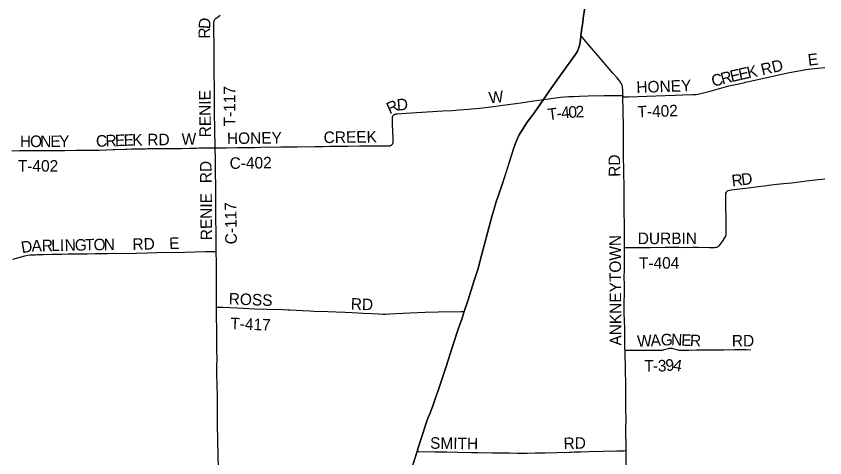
# Model space of a CAD drawing. Extents: x 40529 to 41139, y 15164 to 15584.
# Drawn here: x 40618.2 to 40737.7, y 15293.1 to 15358.4 of the extents above; entities that cross this region are included whole.
import ezdxf

# ---------------------------------------------------------------- set-up
doc = ezdxf.new("R2010")
doc.units = 0
for name, color, linetype in [('GM_X_County_Road', 7, 'Continuous'), ('GM_X_County_Road_Text', 7, 'Continuous'), ('GM_X_State_Route', 7, 'Continuous'), ('GM_X_Township_Road', 7, 'Continuous'), ('GM_X_Township_Road_Text', 7, 'Continuous'), ('SH_Data', 7, 'Continuous')]:
    doc.layers.add(name, color=color, linetype=linetype)

msp = doc.modelspace()

# ---------------------------------------------------------------- linework, layer by layer
at = {"layer": 'GM_X_County_Road'}
msp.add_line((40707.83, 15346.5), (40707.83, 15346.69), dxfattribs=at)
for points in [[(40707.83, 15346.69), (40707.83, 15346.91), (40707.81, 15347.56), (40707.79, 15347.85), (40707.76, 15348.03), (40707.71, 15348.22), (40707.68, 15348.3), (40707.6, 15348.48), (40707.5, 15348.64), (40707.39, 15348.79), (40706.98, 15349.3), (40706.37, 15350), (40704.11, 15352.61), (40703.2, 15353.67), (40702.59, 15354.37), (40701.8, 15355.29), (40701.69, 15355.43), (40701.63, 15355.51)], [(40647.63, 15338.98), (40647.76, 15338.97), (40649.24, 15338.97), (40650.91, 15338.99), (40652.03, 15339), (40653.42, 15339.02), (40654.44, 15339.04), (40657.32, 15339.1), (40658.25, 15339.11), (40659.75, 15339.12), (40662.35, 15339.15), (40663.56, 15339.17), (40664.59, 15339.19), (40665.7, 15339.19), (40667.19, 15339.21), (40668.96, 15339.23), (40671.01, 15339.25), (40673.16, 15339.24), (40673.34, 15339.25), (40673.43, 15339.27), (40673.52, 15339.29), (40673.6, 15339.33), (40673.68, 15339.37), (40673.74, 15339.43), (40673.79, 15339.5), (40673.84, 15339.58), (40673.87, 15339.66), (40673.89, 15339.75), (40673.9, 15339.84), (40673.91, 15340.03), (40673.9, 15340.4), (40673.82, 15342.45), (40673.8, 15343.19), (40673.8, 15343.38), (40673.81, 15343.48), (40673.83, 15343.57), (40673.87, 15343.66), (40673.92, 15343.74), (40673.99, 15343.81), (40674.07, 15343.87), (40674.15, 15343.92), (40674.24, 15343.95), (40674.34, 15343.97), (40674.53, 15343.99), (40675.83, 15344.07), (40681.23, 15344.41), (40682.63, 15344.5), (40683.65, 15344.56), (40685.04, 15344.67), (40685.5, 15344.71), (40686.15, 15344.78), (40687.13, 15344.89), (40688.7, 15345.09), (40690.09, 15345.24), (40692.03, 15345.49), (40692.77, 15345.6), (40693.69, 15345.76), (40694.33, 15345.86), (40694.68, 15345.9), (40695.41, 15346.02), (40695.78, 15346.07), (40696.11, 15346.12)], [(40708.08, 15324.23), (40708.08, 15324.78), (40708.09, 15325.01), (40708.09, 15326.32), (40708.08, 15326.69), (40708.06, 15327.71), (40708.04, 15329.39), (40708.02, 15332.09), (40708, 15333.4), (40707.96, 15335.17), (40707.93, 15338.24), (40707.9, 15342.16), (40707.85, 15344.39), (40707.83, 15346.5)], [(40647.78, 15323.65), (40647.78, 15324.04), (40647.77, 15324.79), (40647.75, 15326.18), (40647.74, 15328.78), (40647.72, 15329.9), (40647.7, 15332.78), (40647.67, 15335.85), (40647.65, 15337.24), (40647.63, 15338.98)], [(40617.73, 15322.51), (40618.27, 15322.64), (40619.53, 15323), (40619.98, 15323.1), (40620.25, 15323.16), (40620.72, 15323.16), (40621.05, 15323.17), (40621.32, 15323.18), (40621.55, 15323.2), (40621.73, 15323.2), (40621.93, 15323.21), (40622.21, 15323.21), (40623.51, 15323.24), (40625, 15323.26), (40625.93, 15323.27), (40627.51, 15323.3), (40627.88, 15323.31), (40628.71, 15323.31), (40629.92, 15323.34), (40631.47, 15323.35), (40631.7, 15323.35), (40632.74, 15323.37), (40632.99, 15323.36), (40635.96, 15323.41), (40637.64, 15323.43), (40639.03, 15323.47), (40643.13, 15323.56), (40646.2, 15323.62), (40647.23, 15323.63), (40647.6, 15323.64), (40647.78, 15323.65)], [(40708.15, 15309.08), (40708.14, 15309.15), (40708.12, 15310.83), (40708.1, 15312.13), (40708.05, 15313.61), (40708.02, 15314.44), (40708.02, 15315.26), (40708.03, 15315.91), (40708.05, 15317.57), (40708.05, 15318.69), (40708.04, 15319.9), (40708.06, 15320.88), (40708.08, 15321.52), (40708.08, 15322.36), (40708.09, 15323.1), (40708.08, 15323.66), (40708.08, 15324.23)], [(40708.32, 15294.22), (40708.31, 15295.05), (40708.29, 15296.81), (40708.29, 15297.37), (40708.3, 15298.86), (40708.28, 15300.25), (40708.27, 15300.9), (40708.27, 15301.16), (40708.27, 15302.73), (40708.25, 15304.22), (40708.22, 15305.89), (40708.15, 15309.08)], [(40708.47, 15279.32), (40708.45, 15279.8), (40708.45, 15280.02), (40708.44, 15280.23), (40708.44, 15280.51), (40708.42, 15283.4), (40708.42, 15283.96), (40708.42, 15284.62), (40708.41, 15286.02), (40708.38, 15287.08), (40708.34, 15289.41), (40708.34, 15289.95), (40708.34, 15290.3), (40708.33, 15290.78), (40708.31, 15291.87), (40708.32, 15292.45), (40708.33, 15294.12), (40708.32, 15294.22)]]:
    msp.add_lwpolyline(points, dxfattribs=at)
at = {"layer": 'GM_X_State_Route'}
for points in [[(40696.32, 15346.42), (40696.93, 15347.32), (40698.39, 15349.37), (40699.26, 15350.58), (40700.4, 15352.17), (40700.77, 15352.71), (40700.98, 15353.02), (40701.11, 15353.24), (40701.24, 15353.51), (40701.34, 15353.78), (40701.41, 15354.06), (40701.47, 15354.34), (40701.52, 15354.61), (40701.61, 15355.35), (40701.63, 15355.51), (40701.78, 15356.64), (40701.9, 15357.47), (40701.99, 15358.12), (40702.25, 15360)], [(40685.84, 15319.2), (40686.08, 15319.94), (40686.42, 15321), (40686.71, 15322.09), (40687.02, 15323.26), (40688.22, 15327.86), (40688.51, 15328.94), (40688.8, 15329.92), (40689.08, 15330.81), (40689.94, 15333.38), (40690.67, 15335.59), (40691.69, 15338.79), (40691.93, 15339.49), (40692.13, 15340.01), (40692.32, 15340.44), (40692.52, 15340.86), (40692.75, 15341.26), (40692.94, 15341.58), (40693.24, 15342.05), (40693.72, 15342.74), (40694.33, 15343.57), (40694.76, 15344.17), (40696.11, 15346.12), (40696.32, 15346.42)], [(40676.69, 15291.75), (40677.45, 15294.1), (40677.67, 15294.78), (40678.66, 15297.97), (40678.87, 15298.59), (40679.03, 15299.02), (40679.25, 15299.54), (40679.56, 15300.27), (40679.78, 15300.84), (40680.08, 15301.71), (40680.55, 15303.11), (40681.72, 15306.64), (40682.68, 15309.58), (40683.51, 15312.15), (40684.08, 15313.8), (40684.4, 15314.79), (40684.96, 15316.48), (40685.84, 15319.2)]]:
    msp.add_lwpolyline(points, dxfattribs=at)
at = {"layer": 'GM_X_Township_Road'}
msp.add_line((40707.83, 15346.69), (40707.83, 15346.5), dxfattribs=at)
for points in [[(40647.63, 15338.98), (40647.63, 15339.19), (40647.62, 15339.83), (40647.59, 15340.94), (40647.56, 15342.24), (40647.53, 15343.63), (40647.52, 15345.12), (40647.52, 15348.1), (40647.5, 15349.59), (40647.47, 15353.5), (40647.44, 15356.94), (40647.44, 15357.5), (40647.45, 15357.59), (40647.47, 15357.67), (40647.5, 15357.76), (40647.54, 15357.84), (40647.58, 15357.92), (40647.63, 15357.99), (40647.69, 15358.06), (40647.76, 15358.12), (40647.9, 15358.24), (40648.37, 15358.54)], [(40707.83, 15346.5), (40708.03, 15346.51), (40708.68, 15346.52), (40711.38, 15346.59), (40714.08, 15346.7), (40715.57, 15346.75), (40716.69, 15346.79), (40718.18, 15346.84), (40718.64, 15346.86), (40718.92, 15346.9), (40719.28, 15346.97), (40719.73, 15347.07), (40720.72, 15347.34), (40722.42, 15347.82), (40723.5, 15348.1), (40724.96, 15348.44), (40725.77, 15348.62), (40725.94, 15348.65), (40726.18, 15348.71), (40727.31, 15348.95), (40728.22, 15349.14), (40731.94, 15349.98), (40733.22, 15350.24), (40734.13, 15350.41), (40734.87, 15350.53), (40735.61, 15350.64), (40736.63, 15350.75), (40737.65, 15350.85)], [(40696.11, 15346.12), (40696.86, 15346.21), (40698.61, 15346.43), (40699.27, 15346.5), (40699.83, 15346.53), (40700.57, 15346.56), (40701.41, 15346.59), (40702.72, 15346.64), (40705.05, 15346.7), (40705.61, 15346.71), (40706.73, 15346.69), (40707.66, 15346.69), (40707.83, 15346.69)], [(40617.58, 15338.54), (40618.74, 15338.58), (40619.94, 15338.57), (40620.42, 15338.56), (40620.68, 15338.56), (40620.91, 15338.56), (40621.09, 15338.56), (40622, 15338.56), (40623.26, 15338.56), (40623.72, 15338.57), (40623.83, 15338.56), (40623.99, 15338.57), (40624.37, 15338.57), (40625.43, 15338.58), (40627.07, 15338.6), (40627.73, 15338.61), (40628.74, 15338.61), (40629.28, 15338.6), (40630.49, 15338.62), (40631.59, 15338.67), (40632.63, 15338.69), (40632.83, 15338.69), (40634.38, 15338.76), (40634.48, 15338.76), (40634.55, 15338.77), (40635.28, 15338.8), (40635.89, 15338.81), (40636.19, 15338.81), (40636.66, 15338.81), (40636.86, 15338.81), (40637.04, 15338.82), (40637.36, 15338.82), (40637.65, 15338.84), (40637.84, 15338.84), (40637.98, 15338.84), (40638.26, 15338.84), (40638.42, 15338.84), (40638.66, 15338.84), (40638.95, 15338.84), (40639.27, 15338.85), (40639.43, 15338.84), (40639.57, 15338.85), (40639.76, 15338.84), (40640.3, 15338.85), (40640.82, 15338.86), (40642.64, 15338.88), (40643.82, 15338.91), (40644.86, 15338.93), (40645.24, 15338.94), (40645.43, 15338.94), (40646.55, 15338.97), (40647.2, 15338.98), (40647.48, 15338.98), (40647.63, 15338.98)], [(40708.08, 15324.23), (40708.22, 15324.24), (40709.06, 15324.25), (40710.46, 15324.25), (40711.92, 15324.25), (40714.09, 15324.26), (40715.49, 15324.27), (40716.15, 15324.27), (40717.15, 15324.25), (40718.09, 15324.26), (40718.93, 15324.27), (40720.61, 15324.25), (40721.1, 15324.25), (40721.39, 15324.25), (40721.57, 15324.27), (40721.74, 15324.3), (40721.86, 15324.34), (40721.97, 15324.41), (40722.03, 15324.46), (40722.1, 15324.54), (40722.2, 15324.66), (40722.33, 15324.85), (40722.52, 15325.14), (40722.87, 15325.66), (40723.01, 15325.89), (40723.04, 15325.97), (40723.07, 15326.05), (40723.09, 15326.22), (40723.1, 15326.39), (40723.09, 15326.66), (40723.08, 15327.03), (40723.08, 15327.22), (40723.07, 15327.4), (40723.07, 15327.67), (40723.06, 15327.98), (40723.06, 15328.47), (40723.05, 15330.32), (40723.03, 15331.44), (40723.04, 15332.09), (40723.04, 15332.18), (40723.05, 15332.27), (40723.11, 15332.43), (40723.17, 15332.51), (40723.24, 15332.56), (40723.31, 15332.62), (40723.4, 15332.67), (40723.59, 15332.7), (40723.85, 15332.73), (40724.66, 15332.83), (40725.96, 15332.98), (40728.26, 15333.28), (40728.81, 15333.36), (40729.31, 15333.43), (40729.8, 15333.51), (40730.57, 15333.59), (40731.55, 15333.68), (40732.75, 15333.81), (40735.34, 15334.12), (40737.65, 15334.38)], [(40647.84, 15315.41), (40647.83, 15316.48), (40647.84, 15317.78), (40647.81, 15319.08), (40647.8, 15320.85), (40647.81, 15321.68), (40647.8, 15322.06), (40647.78, 15323.54), (40647.78, 15323.65)], [(40648.34, 15278.15), (40648.33, 15279.06), (40648.3, 15281.66), (40648.25, 15285.2), (40648.21, 15286.87), (40648.18, 15288.73), (40648.16, 15289.66), (40648.13, 15291.34), (40648.08, 15293.67), (40648.04, 15295.52), (40647.98, 15298.33), (40647.97, 15300.28), (40647.95, 15302.23), (40647.88, 15305.57), (40647.89, 15306.52), (40647.9, 15307.91), (40647.87, 15308.93), (40647.86, 15310.14), (40647.85, 15310.43), (40647.85, 15310.89), (40647.86, 15312.19), (40647.84, 15313.87), (40647.84, 15314.8), (40647.84, 15315.41)], [(40647.84, 15315.41), (40647.97, 15315.41), (40648.81, 15315.39), (40650.85, 15315.3), (40653.46, 15315.19), (40655.23, 15315.12), (40657.65, 15315.05), (40658.38, 15315.02), (40658.65, 15315), (40660.51, 15314.92), (40661.62, 15314.86), (40662.18, 15314.82), (40664.31, 15314.75), (40665.51, 15314.71), (40666.81, 15314.65), (40667.84, 15314.6), (40669.5, 15314.53), (40670.71, 15314.47), (40671.74, 15314.42), (40672.39, 15314.4), (40672.85, 15314.4), (40673.41, 15314.42), (40676.38, 15314.57), (40677.5, 15314.63), (40678.62, 15314.67), (40680.57, 15314.72), (40683.93, 15314.78), (40684.4, 15314.79)], [(40708.15, 15309.08), (40708.83, 15309.08), (40710.28, 15309.05), (40712.6, 15309.05), (40713.06, 15309.05), (40713.48, 15309.05), (40713.64, 15309.07), (40713.82, 15309.11), (40713.95, 15309.14), (40714.17, 15309.2), (40714.39, 15309.26), (40714.59, 15309.32), (40714.68, 15309.34), (40714.78, 15309.35), (40714.89, 15309.35), (40714.97, 15309.35), (40715.09, 15309.33), (40715.21, 15309.3), (40715.39, 15309.25), (40715.78, 15309.14), (40715.92, 15309.1), (40716.08, 15309.08), (40716.38, 15309.06), (40717.02, 15309.06), (40717.56, 15309.06), (40718.7, 15309.1), (40719.36, 15309.11), (40719.88, 15309.13), (40722.71, 15309.13), (40724.33, 15309.14), (40725.51, 15309.16), (40726.1, 15309.17), (40726.71, 15309.13)], [(40677.45, 15294.1), (40677.7, 15294.1), (40680.03, 15294.05), (40681.8, 15294.02), (40683.47, 15294), (40685.52, 15293.95), (40686.45, 15293.93), (40688.59, 15293.91), (40690.07, 15293.91), (40691.1, 15293.89), (40692.21, 15293.85), (40692.76, 15293.85), (40693.69, 15293.86), (40694.9, 15293.87), (40696.37, 15293.89), (40698.14, 15293.95), (40699.9, 15293.99), (40700.18, 15293.99), (40700.64, 15294.01), (40701.57, 15294.04), (40702.78, 15294.08), (40704.91, 15294.13), (40706.95, 15294.16), (40707.41, 15294.18), (40707.76, 15294.19), (40708.03, 15294.2), (40708.2, 15294.22), (40708.32, 15294.22)]]:
    msp.add_lwpolyline(points, dxfattribs=at)
at = {"layer": 'SH_Data'}
msp.add_lwpolyline([(40702.25, 15360), (40701.99, 15358.12), (40701.9, 15357.47), (40701.78, 15356.64), (40701.63, 15355.51), (40701.56, 15354.98), (40701.52, 15354.61), (40701.47, 15354.34), (40701.41, 15354.06), (40701.34, 15353.78), (40701.24, 15353.51), (40701.11, 15353.24), (40700.98, 15353.02), (40700.77, 15352.71), (40700.4, 15352.17), (40699.26, 15350.58), (40698.39, 15349.37), (40696.93, 15347.32), (40696.32, 15346.42), (40696.11, 15346.12), (40694.76, 15344.17), (40694.76, 15344.17), (40694.33, 15343.57), (40693.72, 15342.74), (40693.24, 15342.05), (40692.94, 15341.58), (40692.75, 15341.26), (40692.52, 15340.86), (40692.32, 15340.44), (40692.13, 15340.01), (40691.93, 15339.49), (40691.69, 15338.79), (40689.94, 15333.38), (40689.08, 15330.81), (40688.8, 15329.92), (40688.51, 15328.94), (40688.22, 15327.86), (40687.02, 15323.26), (40686.71, 15322.09), (40686.42, 15321), (40686.08, 15319.94), (40685.84, 15319.2), (40684.96, 15316.48), (40684.4, 15314.79), (40684.08, 15313.8), (40683.51, 15312.15), (40682.68, 15309.58), (40681.72, 15306.64), (40680.55, 15303.11), (40680.08, 15301.71), (40679.78, 15300.84), (40679.56, 15300.27), (40679.25, 15299.54), (40679.03, 15299.02), (40678.87, 15298.59), (40678.66, 15297.97), (40677.67, 15294.78), (40676.69, 15291.75)], dxfattribs=at)

# ---------------------------------------------------------------- texts
at = {"layer": 'GM_X_County_Road_Text'}
for s, height, rotation, p in [('W', 1.71, 6.5, (40688.13, 15345.5)), ('R', 1.71, 24.2359, (40673.38, 15343.91)), ('D', 1.71, 4.5271, (40674.51, 15344.45)), ('HONEY', 1.706, 0.771, (40649.37, 15339.5)), ('CREEK', 1.706, 0.8333, (40663.65, 15339.65)), ('C-402', 1.706, 0.831, (40649.77, 15335.84)), ('RD', 1.706, 90.9872, (40707.46, 15334.69)), ('RD', 1.706, 90.4848, (40647.1, 15333.74)), ('RENIE', 1.706, 90.4655, (40647.18, 15325.31)), ('C-117', 1.706, 90.8145, (40650.83, 15324.71)), ('N', 1.71, 1.0411, (40625.41, 15323.72)), ('G', 1.71, 1.0382, (40626.91, 15323.75)), ('T', 1.71, 1.0393, (40628.41, 15323.78)), ('O', 1.71, 1.0382, (40629.68, 15323.8)), ('N', 1.71, 0.714, (40631.18, 15323.83)), ('RD', 1.706, 0.9085, (40635.42, 15323.88)), ('E', 1.71, 2.2444, (40640.86, 15323.98)), ('ANKNEYTOWN', 1.706, 90.2862, (40707.61, 15309.74)), ('D', 1.71, 9.8199, (40619.12, 15323.38)), ('A', 1.71, 1.235, (40620.53, 15323.63)), ('R', 1.71, 1.0402, (40622.03, 15323.66)), ('L', 1.71, 1.0393, (40623.43, 15323.69)), ('I', 1.71, 1.0382, (40624.71, 15323.71))]:
    msp.add_text(s, height=height, rotation=rotation, dxfattribs=at).set_placement(p)
at = {"layer": 'GM_X_Township_Road_Text'}
for s, height, rotation, p in [('D', 1.71, 85.5732, (40646.86, 15356.47)), ('R', 1.71, 90.5659, (40646.88, 15355.11)), ('E', 1.71, 6.7136, (40735.24, 15351.08)), ('RD', 1.706, 12.9582, (40728.42, 15349.67)), ('E', 1.71, 12.8928, (40723.86, 15348.66)), ('E', 1.71, 12.4988, (40725.1, 15348.95)), ('K', 1.71, 12.4952, (40726.35, 15349.22)), ('C', 1.71, 15.123, (40721.16, 15347.96)), ('R', 1.71, 14.1574, (40722.51, 15348.32)), ('HONEY', 1.706, 1.9452, (40709.85, 15347.06)), ('RENIE', 1.706, 90.4709, (40647, 15340.52)), ('T-117', 1.706, 90, (40650.58, 15342.13)), ('T', 1.71, 7.4025, (40696.85, 15343.03)), ('4', 1.71, 5.6189, (40698.8, 15343.28)), ('0', 1.71, 2.6264, (40699.82, 15343.38)), ('2', 1.71, 2.3034, (40700.87, 15343.43)), ('T-402', 1.706, 1.9466, (40710.01, 15343.43)), ('-', 1.71, 7.1182, (40698.12, 15343.19)), ('E', 1.71, 1.8281, (40634.13, 15339.24)), ('K', 1.71, 0.8142, (40635.39, 15339.28)), ('RD', 1.706, 0.4786, (40637.61, 15339.32)), ('W', 1.71, 0.7248, (40642.68, 15339.4)), ('H', 1.71, 0, (40618.79, 15339.07)), ('O', 1.71, 0, (40620.29, 15339.07)), ('N', 1.71, 0, (40621.79, 15339.07)), ('E', 1.71, 0.0341, (40623.29, 15339.07)), ('Y', 1.71, 0.8721, (40624.6, 15339.08)), ('C', 1.71, 1.9498, (40630.05, 15339.1)), ('R', 1.71, 1.9529, (40631.45, 15339.15)), ('E', 1.71, 1.9481, (40632.85, 15339.19)), ('T-402', 1.706, 0, (40618.49, 15335.44)), ('R', 1.71, 6.6675, (40723.99, 15333.24)), ('D', 1.71, 7.7998, (40725.42, 15333.41)), ('DURBIN', 1.706, 0, (40710.03, 15324.73)), ('T-404', 1.706, 0.2794, (40710.21, 15321.08)), ('ROSS', 1.706, 357.8054, (40649.6, 15315.82)), ('RD', 1.706, 357.5801, (40667.62, 15315.07)), ('T-417', 1.706, 357.7547, (40649.84, 15312.17)), ('W', 1.71, 3.2955, (40709.99, 15309.52)), ('A', 1.71, 3.293, (40711.96, 15309.63)), ('G', 1.71, 2.8917, (40713.46, 15309.72)), ('N', 1.71, 357.6935, (40714.92, 15309.79)), ('E', 1.71, 356.9944, (40716.41, 15309.73)), ('R', 1.71, 357.2559, (40717.7, 15309.67)), ('RD', 1.706, 0.4934, (40723.93, 15309.59)), ('T', 1.71, 0.0343, (40710.98, 15305.89)), ('3', 1.71, 1.9411, (40713.02, 15305.89)), ('9', 1.71, 7.3877, (40714.25, 15305.94)), ('4', 1.71, 350.4273, (40715.16, 15306.08)), ('-', 1.71, 0.3614, (40712.27, 15305.89)), ('SMITH', 1.706, 359.1311, (40679.35, 15294.5)), ('RD', 1.706, 1.4316, (40699.09, 15294.43))]:
    msp.add_text(s, height=height, rotation=rotation, dxfattribs=at).set_placement(p)

doc.saveas('drawing.dxf')
